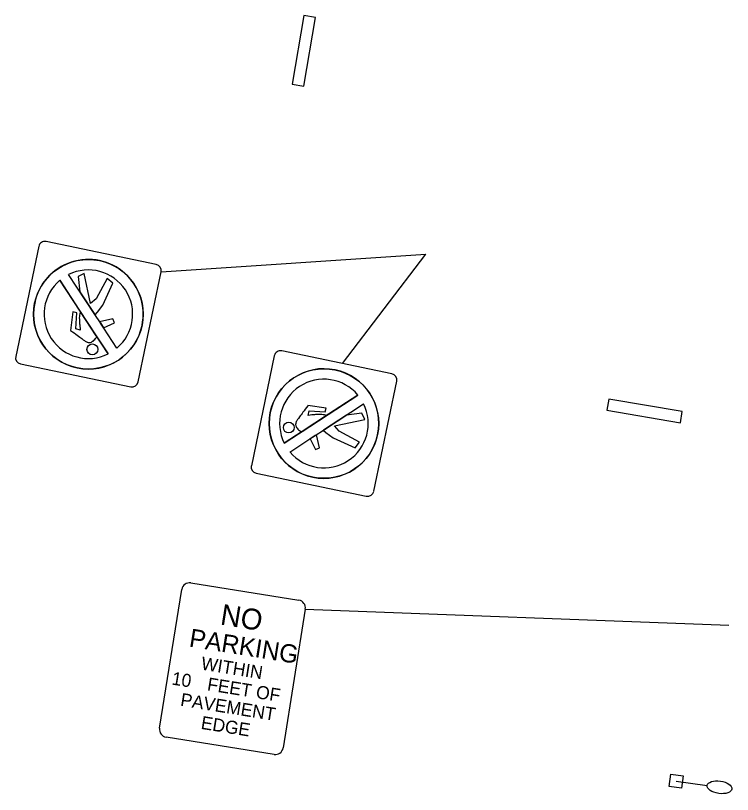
# Model space of a CAD drawing. Extents: x 1482113 to 1482447, y 365324 to 365634.
# Drawn here: x 1482169.1 to 1482283.8, y 365366.6 to 365491.2 of the extents above; entities that cross this region are included whole.
import ezdxf

# ---------------------------------------------------------------- set-up
doc = ezdxf.new("R2010")
doc.units = 0
for name, color, linetype in [('_CIVIL_CONSTRUCTION', 7, 'Continuous'), ('RS_Raster1', 7, 'Continuous'), ('RW_X_CL', 7, 'Continuous'), ('RW_X_CL_500_Bearings', 7, 'Continuous')]:
    doc.layers.add(name, color=color, linetype=linetype)

msp = doc.modelspace()

# ---------------------------------------------------------------- linework, layer by layer
at = {"layer": '_CIVIL_CONSTRUCTION'}
for points in [[(1482215.2, 365479.92), (1482217.06, 365490.91), (1482215.19, 365491.23), (1482213.34, 365480.24)], [(1482275.76, 365427.85), (1482263.98, 365429.84), (1482263.68, 365428.06), (1482275.46, 365426.06)]]:
    msp.add_lwpolyline(points, close=True, dxfattribs=at)
at = {"layer": 'RS_Raster1'}
msp.add_line((1482215.44, 365396.23), (1482283.21, 365393.65), dxfattribs=at)
for points in [[(1482197.13, 365400.43), (1482214.4, 365397.67)], [(1482192.13, 365377.18), (1482195.69, 365399.4)], [(1482215.44, 365396.23), (1482211.88, 365374.02)], [(1482210.45, 365372.98), (1482193.17, 365375.75)]]:
    msp.add_lwpolyline(points, dxfattribs=at)
for centre, start, end in [((1482196.93, 365399.2), 80.9, 170.9), ((1482214.21, 365396.43), 350.9, 80.9), ((1482193.37, 365376.98), 170.9, 260.9), ((1482210.65, 365374.22), 260.9, 350.9)]:
    msp.add_arc(centre, 1.25, start, end, dxfattribs=at)
at = {"layer": 'RW_X_CL'}
msp.add_line((1482274.79, 365368.7), (1482279.74, 365368), dxfattribs=at)
msp.add_lwpolyline([(1482273.94, 365369.83), (1482275.92, 365369.55), (1482275.64, 365367.57), (1482273.66, 365367.85)], close=True, dxfattribs=at)
msp.add_ellipse((1482281.72, 365367.73), major_axis=(1.98, -0.28), ratio=0.5, dxfattribs=at)
at = {"layer": 'RW_X_CL_500_Bearings'}
for p, q in [((1482192.36, 365450.22), (1482234.7, 365453.04)), ((1482221.37, 365435.54), (1482234.7, 365453.04)), ((1482180.08, 365449.97), (1482179.08, 365449.49)), ((1482180.08, 365449.97), (1482179.08, 365449.49)), ((1482181.09, 365445.15), (1482180.08, 365449.97)), ((1482181.09, 365445.15), (1482180.08, 365449.97)), ((1482183.88, 365437.08), (1482176.17, 365448.87)), ((1482179.08, 365449.49), (1482179.38, 365447.03)), ((1482179.08, 365449.49), (1482179.38, 365447.03)), ((1482183.72, 365449.13), (1482181.97, 365445.89)), ((1482183.72, 365449.13), (1482181.97, 365445.89)), ((1482184.62, 365448.42), (1482183.72, 365449.13)), ((1482184.62, 365448.42), (1482183.72, 365449.13)), ((1482183.03, 365444.89), (1482184.62, 365448.42)), ((1482183.03, 365444.89), (1482184.62, 365448.42)), ((1482179.38, 365447.03), (1482181.77, 365443.38)), ((1482181.97, 365445.89), (1482181.09, 365445.15)), ((1482181.97, 365445.89), (1482181.09, 365445.15)), ((1482182.18, 365443.76), (1482183.03, 365444.89)), ((1482182.18, 365443.76), (1482183.03, 365444.89)), ((1482178.26, 365443.81), (1482177.88, 365440.84)), ((1482178.26, 365443.81), (1482177.88, 365440.84)), ((1482178.88, 365443.63), (1482178.26, 365443.81)), ((1482178.88, 365443.63), (1482178.26, 365443.81)), ((1482178.72, 365441.07), (1482178.88, 365443.63)), ((1482178.72, 365441.07), (1482178.88, 365443.63)), ((1482181.99, 365439.98), (1482179.49, 365443.79)), ((1482181.82, 365443.31), (1482182.18, 365443.76)), ((1482181.82, 365443.31), (1482182.18, 365443.76)), ((1482181.77, 365443.38), (1482181.82, 365443.31)), ((1482184.64, 365442.72), (1482182.53, 365442.22)), ((1482184.64, 365442.72), (1482182.53, 365442.22)), ((1482182.53, 365442.22), (1482182.66, 365442.03)), ((1482184.92, 365442.06), (1482184.64, 365442.72)), ((1482184.92, 365442.06), (1482184.64, 365442.72)), ((1482179.43, 365440.89), (1482178.72, 365441.07)), ((1482179.43, 365440.89), (1482178.72, 365441.07)), ((1482183.17, 365441.25), (1482184.92, 365442.06)), ((1482183.17, 365441.25), (1482184.92, 365442.06)), ((1482177.88, 365440.84), (1482177.89, 365440.83)), ((1482177.88, 365440.84), (1482177.89, 365440.83)), ((1482182.07, 365439.85), (1482181.99, 365439.98)), ((1482212.07, 365422.79), (1482223.85, 365430.5)), ((1482218.8, 365428.41), (1482215.82, 365428.8)), ((1482215.82, 365428.8), (1482215.82, 365428.78)), ((1482218.8, 365428.41), (1482215.82, 365428.8)), ((1482215.82, 365428.8), (1482215.82, 365428.78)), ((1482215.88, 365427.25), (1482216.06, 365427.96)), ((1482215.88, 365427.25), (1482216.06, 365427.96)), ((1482216.06, 365427.96), (1482218.61, 365427.8)), ((1482216.06, 365427.96), (1482218.61, 365427.8)), ((1482222.02, 365427.3), (1482218.37, 365424.9)), ((1482218.61, 365427.8), (1482218.8, 365428.41)), ((1482218.61, 365427.8), (1482218.8, 365428.41)), ((1482224.48, 365427.6), (1482222.02, 365427.3)), ((1482224.48, 365427.6), (1482222.02, 365427.3)), ((1482224.95, 365426.59), (1482224.48, 365427.6)), ((1482224.95, 365426.59), (1482224.48, 365427.6)), ((1482214.96, 365424.69), (1482218.78, 365427.18)), ((1482220.13, 365425.59), (1482224.95, 365426.59)), ((1482220.13, 365425.59), (1482224.95, 365426.59)), ((1482218.37, 365424.9), (1482218.3, 365424.86)), ((1482218.3, 365424.86), (1482218.74, 365424.49)), ((1482218.3, 365424.86), (1482218.74, 365424.49)), ((1482220.87, 365424.7), (1482220.13, 365425.59)), ((1482220.87, 365424.7), (1482220.13, 365425.59)), ((1482214.84, 365424.61), (1482214.96, 365424.69)), ((1482217.21, 365424.14), (1482217.01, 365424.02)), ((1482217.7, 365422.04), (1482217.21, 365424.14)), ((1482217.7, 365422.04), (1482217.21, 365424.14)), ((1482218.74, 365424.49), (1482219.88, 365423.64)), ((1482218.74, 365424.49), (1482219.88, 365423.64)), ((1482219.88, 365423.64), (1482223.4, 365422.06)), ((1482219.88, 365423.64), (1482223.4, 365422.06)), ((1482224.11, 365422.96), (1482220.87, 365424.7)), ((1482224.11, 365422.96), (1482220.87, 365424.7)), ((1482216.23, 365423.5), (1482217.05, 365421.76)), ((1482216.23, 365423.5), (1482217.05, 365421.76)), ((1482223.4, 365422.06), (1482224.11, 365422.96)), ((1482223.4, 365422.06), (1482224.11, 365422.96)), ((1482217.05, 365421.76), (1482217.7, 365422.04)), ((1482217.05, 365421.76), (1482217.7, 365422.04))]:
    msp.add_line(p, q, dxfattribs=at)
for points in [[(1482191.59, 365451.4), (1482173.96, 365455.07)], [(1482172.78, 365454.3), (1482169.11, 365436.68)], [(1482182.66, 365442.03), (1482181.77, 365443.38), (1482178.9, 365447.76), (1482177.57, 365449.78)], [(1482188.68, 365432.59), (1482192.36, 365450.22)], [(1482176.17, 365448.86), (1482179.23, 365444.19), (1482179.23, 365444.19), (1482179.23, 365444.19), (1482181.99, 365439.98), (1482181.99, 365439.98)], [(1482185.3, 365438.01), (1482183.2, 365441.21), (1482182.65, 365442.02), (1482182.66, 365442.03)], [(1482182.66, 365442.03), (1482183.17, 365441.25), (1482183.17, 365441.25)], [(1482181.99, 365439.98), (1482183.88, 365437.08)], [(1482181.99, 365439.98), (1482181.99, 365439.98)], [(1482229.28, 365433.89), (1482211.66, 365437.57)], [(1482210.48, 365436.79), (1482206.81, 365419.17)], [(1482169.88, 365435.49), (1482187.5, 365431.82)], [(1482226.38, 365415.09), (1482230.06, 365432.71)], [(1482223.85, 365430.5), (1482219.17, 365427.44), (1482219.18, 365427.44), (1482219.17, 365427.44), (1482214.96, 365424.69), (1482214.97, 365424.69)], [(1482217.01, 365424.02), (1482218.37, 365424.9), (1482222.75, 365427.78), (1482224.77, 365429.1)], [(1482214.96, 365424.69), (1482212.07, 365422.79)], [(1482212.99, 365421.38), (1482216.19, 365423.48), (1482217.01, 365424.02), (1482217.01, 365424.02)], [(1482214.96, 365424.69), (1482214.96, 365424.69)], [(1482217.01, 365424.02), (1482216.23, 365423.5), (1482216.23, 365423.5)], [(1482207.58, 365417.99), (1482225.2, 365414.31)]]:
    msp.add_lwpolyline(points, dxfattribs=at)
for centre, radius in [((1482180.73, 365443.43), 8.77), ((1482181.37, 365437.81), 0.864), ((1482218.42, 365425.94), 8.77), ((1482212.8, 365425.3), 0.864)]:
    msp.add_circle(centre, radius, dxfattribs=at)
for centre, radius, start, end in [((1482173.76, 365454.09), 1, 78.219, 168.219), ((1482180.73, 365443.43), 8.77, 348.219, 168.219), ((1482191.38, 365450.42), 1, 348.219, 78.219), ((1482180.73, 365443.43), 7.09, 310.0669, 116.4669), ((1482180.73, 365443.43), 7.09, 310.0669, 116.4669), ((1482180.73, 365443.43), 7.09, 130.038, 296.3903), ((1482180.73, 365443.43), 7.09, 130.038, 296.3903), ((1482180.73, 365443.43), 8.77, 168.219, 348.219), ((1482180.99, 365441.15), 1.54, 310.2941, 310.3473), ((1482211.46, 365436.59), 1, 78.219, 168.219), ((1482170.08, 365436.47), 1, 168.219, 258.219), ((1482218.42, 365425.94), 8.77, 78.219, 258.219), ((1482218.42, 365425.94), 8.77, 258.219, 78.219), ((1482229.08, 365432.91), 1, 348.219, 78.219), ((1482187.71, 365432.8), 1, 258.219, 348.219), ((1482218.42, 365425.94), 7.09, 40.038, 206.3903), ((1482218.42, 365425.94), 7.09, 40.038, 206.3903), ((1482218.42, 365425.94), 7.09, 220.0669, 26.4669), ((1482218.42, 365425.94), 7.09, 220.0669, 26.4669), ((1482216.14, 365425.68), 1.54, 220.2941, 220.3473), ((1482207.78, 365418.97), 1, 168.219, 258.219), ((1482225.41, 365415.29), 1, 258.219, 348.219)]:
    msp.add_arc(centre, radius, start, end, dxfattribs=at)
for points in [[(1482179.49, 365443.79), (1482179.45, 365443.73), (1482179.34, 365443.54), (1482179.28, 365443.08), (1482179.28, 365442.66), (1482179.33, 365441.91), (1482179.37, 365441.39), (1482179.43, 365440.89)], [(1482179.49, 365443.79), (1482179.45, 365443.73), (1482179.34, 365443.54), (1482179.28, 365443.08), (1482179.28, 365442.66), (1482179.33, 365441.91), (1482179.37, 365441.39), (1482179.43, 365440.89)], [(1482177.89, 365440.83), (1482178.68, 365440.27), (1482179.91, 365439.37), (1482180.36, 365439.04), (1482180.52, 365438.97), (1482180.68, 365438.94), (1482181.07, 365438.85), (1482181.66, 365439.22), (1482181.91, 365439.61), (1482182.07, 365439.85)], [(1482177.89, 365440.83), (1482178.68, 365440.27), (1482179.91, 365439.37), (1482180.36, 365439.04), (1482180.52, 365438.97), (1482180.68, 365438.94), (1482181.07, 365438.85), (1482181.66, 365439.22), (1482181.91, 365439.61), (1482182.07, 365439.85)], [(1482215.82, 365428.78), (1482215.26, 365428), (1482214.36, 365426.77), (1482214.02, 365426.32), (1482213.96, 365426.16), (1482213.92, 365425.99), (1482213.84, 365425.6), (1482214.2, 365425.01), (1482214.6, 365424.76), (1482214.84, 365424.61)], [(1482215.82, 365428.78), (1482215.26, 365428), (1482214.36, 365426.77), (1482214.02, 365426.32), (1482213.96, 365426.16), (1482213.92, 365425.99), (1482213.84, 365425.6), (1482214.2, 365425.01), (1482214.6, 365424.76), (1482214.84, 365424.61)], [(1482218.78, 365427.18), (1482218.71, 365427.23), (1482218.53, 365427.33), (1482218.07, 365427.39), (1482217.65, 365427.4), (1482216.9, 365427.35), (1482216.38, 365427.3), (1482215.88, 365427.25)], [(1482218.78, 365427.18), (1482218.71, 365427.23), (1482218.53, 365427.33), (1482218.07, 365427.39), (1482217.65, 365427.4), (1482216.9, 365427.35), (1482216.38, 365427.3), (1482215.88, 365427.25)]]:
    msp.add_open_spline(points, degree=3, dxfattribs=at)

# ---------------------------------------------------------------- texts
at = {"layer": 'RS_Raster1'}
for s, height, p in [('NO', 3.333, (1482201.71, 365393.79)), ('PARKING', 2.917, (1482196.73, 365390.26)), ('WITHIN', 2.083, (1482198.67, 365386.58)), ('10', 2.083, (1482193.97, 365384.18)), ('FEET OF', 2.083, (1482199.65, 365383.26)), ('PAVEMENT', 2.083, (1482195.36, 365380.78)), ('EDGE', 2.083, (1482198.64, 365377.09))]:
    msp.add_text(s, height=height, rotation=350.9, dxfattribs=at).set_placement(p)

doc.saveas('drawing.dxf')
